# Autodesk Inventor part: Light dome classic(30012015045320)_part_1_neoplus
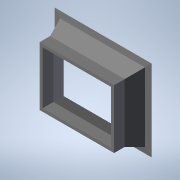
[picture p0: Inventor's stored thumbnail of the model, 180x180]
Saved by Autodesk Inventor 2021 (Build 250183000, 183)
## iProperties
Created: 2026-04
Part Number: Light dome classic(30012015045320)_part_1_neoplus
Material: Generic
Catalog Web Link: www.3dfindit.com
Description: Light dome classic_part_1_neoplus-
Vendor: KINGSPAN
Document SubType Name: Modeling
Designer: psAdmin
Manufacturer: KINGSPAN
Mass: 152663 g
Surface Area: 72270.1 cm^2
Volume: 152663 cm^3
Density: 1 g/cm^3
Appearance: PSOLRGB-255-255-255
Category: PARTsolutions
Company: KINGSPAN
Title: Light dome classic(30012015045320)_part_1_neoplus
Author: Cadenas PARTsolutions
PSOL_IDENT_0: {$CADENAS_DATA/23d-libs/kingspan_kla/light_dome_classic_neoplus/parts/part_1.prj},297 {VTYP=3D},{NB=
PSOL_IDENT_1: Light dome classic(30012015045320)_part_1_neoplus},{LINA=Light dome classic(30012015045320)_part_1_n
PSOL_IDENT_2: eoplus},{NN=Light dome classic_part_1_neoplus},{DATE=20.03.2025 09:30:52},{GEOMDATE=03.07.2024 07:48
PSOL_IDENT_3: :00},{VERSION=},{LINEID=10},{WBVAR=LODLEVEL,L,W,DP,OP,BA,INS,RT},{WBNUMERIC=W,RT}  {NB=Light dome cl
PSOL_IDENT_4: assic(30012015045320)_part_1_neoplus},{LINA=Light dome classic(30012015045320)_part_1_neoplus},{KT=D
PSOL_IDENT_5: UMMY},{IDNR=},{PN=Light dome classic},{LODLEVEL=300},{L=120},{W=150},{DRIVE=1},{WX=120,150,180,240,2
PSOL_IDENT_6: 70,300},{DP=4},{OP=5},{BA=3},{INS=2},{INSX='2','without insulation'},{OPX='5','Pneumatic - NRWG F.6
PSOL_IDENT_7: LK'},{LX=1200},{XWX=1500},{HEI=1181.607},{BAX='1', 'PVC base 15 cm','2', 'PVC base 30 cm', '3', 'PVC
PSOL_IDENT_8: base 50 cm' , '4', 'Metal base single skin (steel), 30 cm', '5' , 'Metal base single skin (steel),
PSOL_IDENT_9: 40 cm', '6' , 'Metal base single skin (steel), 50 cm', '7' , 'Metal base double skin (aluminum), 30
PSOL_IDENT_10: cm', '8' , 'Metal base double skin (aluminum), 40 cm', '9' , 'Metal base double skin (aluminum), 50
PSOL_IDENT_11: cm', '10', 'Steel base 30 cm', '11' , 'Steel base 40 cm', '12', 'Steel base 50 cm', '13' , 'AK30 AL/
PSOL_IDENT_12: AL', '14' , 'AK40 AL/AL', '15' , 'AK50 AL/AL', '16' , 'AK50 ST-TG'},{RT=0}
NB: Light dome classic(30012015045320)_part_1_neoplus
NN: Light dome classic_part_1_neoplus
NBSYN: $PN.($LODLEVEL.$L.$W.$DP.$OP.$BA.$INS.$RT.)_part_1_neoplus
LINA: Light dome classic(30012015045320)_part_1_neoplus
CATALOG: Light + Air
PN: Light dome classic
LODLEVEL: 300
L: 120
W: 150
DP: NSHE
OP: Pneumatic - NRWG F.6 LK
BA: PVC base 50 cm
INS: without insulation
RT: 0
SUPPLIER: KINGSPAN
ARTICLENO: Light dome classic(30012015045320)_part_1_neoplus
BOMINFO: Light dome classic(30012015045320)_part_1_neoplus
CREATOR: CADENAS GmbH
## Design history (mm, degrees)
sketch "Sketch_1"
  geometry: L1 (-650.529, 500)-(-707.495, 500); L2 (-707.495, 500)-(-707.495, 300); L3 (-707.495, 300)-(-805.041, 12.062); L4 (-805.041, 12.062)-(-920.088, 1.996); L5 (-920.001, 0)-(-750, 0); L6 (-750, 0)-(-650.529, 293.622); L7 (-650.529, 293.622)-(-650.529, 500); A1 r 1 centre (-920.001, 1) between (-920.088, 1.996) and (-920.001, 0)
  constraints: 14 end point, 2 point on circle, 1 centre point
extrude "Extrusion1" join sketch "Sketch_1" stored distance "d0" = 2400; taper "d1" = 0 deg
sketch "Sketch_2"
  geometry: L1 (500.529, 500)-(500.529, 293.622); L2 (500.529, 293.622)-(600, 0); L3 (600, 0)-(770.001, 0); L4 (770.088, 1.996)-(655.041, 12.062); L5 (655.041, 12.062)-(557.495, 300); L6 (557.495, 300)-(557.495, 500); L7 (557.495, 500)-(500.529, 500); A1 r 1 centre (770.001, 1) between (770.001, 0) and (770.088, 1.996)
  constraints: 14 end point, 2 point on circle, 1 centre point
extrude "Extrusion2" join sketch "Sketch_2" stored distance "d2" = 3000; taper "d3" = 0 deg
sketch "Sketch_3"
  geometry: L1 (920.088, 1.996)-(805.041, 12.062); L2 (805.041, 12.062)-(707.495, 300); L3 (707.495, 300)-(707.495, 500); L4 (707.495, 500)-(650.529, 500); L5 (650.529, 500)-(650.529, 293.622); L6 (650.529, 293.622)-(750, 0); L7 (750, 0)-(920.001, 0); A1 r 1 centre (920.001, 1) between (920.001, 0) and (920.088, 1.996)
  constraints: 14 end point, 2 point on circle, 1 centre point
extrude "Extrusion3" join sketch "Sketch_3" stored distance "d4" = 2400; taper "d5" = 0 deg
sketch "Sketch_4"
  geometry: L1 (-500.529, 500)-(-557.495, 500); L2 (-557.495, 500)-(-557.495, 300); L3 (-557.495, 300)-(-655.041, 12.062); L4 (-655.041, 12.062)-(-770.088, 1.996); L5 (-770.001, 0)-(-600, 0); L6 (-600, 0)-(-500.529, 293.622); L7 (-500.529, 293.622)-(-500.529, 500); A1 r 1 centre (-770.001, 1) between (-770.088, 1.996) and (-770.001, 0)
  constraints: 14 end point, 2 point on circle, 1 centre point
extrude "Extrusion4" join sketch "Sketch_4" stored distance "d6" = 3000; taper "d7" = 0 deg
sketch "Sketch_5"
  geometry: L1 (-650, 600)-(-1500, 600); L2 (-1500, 600)-(-1500, -30); L3 (-1500, -30)-(-819.29, -30); L4 (-819.29, -30)-(-809.127, 0); L5 (-809.127, 0)-(-920.001, 0); L6 (-920.088, 1.996)-(-805.041, 12.062); L7 (-805.041, 12.062)-(-707.495, 300); L8 (-707.495, 300)-(-707.495, 500); L9 (-707.495, 500)-(-650, 500); L10 (-650, 500)-(-650, 600); A1 r 1 centre (-920.001, 1) between (-920.088, 1.996) and (-920.001, 0)
  constraints: 20 end point, 2 point on circle, 1 centre point
extrude "Extrusion5" cut sketch "Sketch_5" stored distance "d8" = 2400; taper "d9" = 0 deg
sketch "Sketch_6"
  geometry: L1 (1500, -30)-(1500, 600); L2 (1500, 600)-(650, 600); L3 (650, 600)-(650, 500); L4 (650, 500)-(707.495, 500); L5 (707.495, 500)-(707.495, 300); L6 (707.495, 300)-(805.041, 12.062); L7 (805.041, 12.062)-(920.088, 1.996); L8 (920.001, 0)-(809.127, 0); L9 (809.127, 0)-(819.29, -30); L10 (819.29, -30)-(1500, -30); A1 r 1 centre (920.001, 1) between (920.001, 0) and (920.088, 1.996)
  constraints: 20 end point, 2 point on circle, 1 centre point
extrude "Extrusion6" cut sketch "Sketch_6" stored distance "d10" = 2400; taper "d11" = 0 deg
sketch "Sketch_7"
  geometry: L1 (1200, 600)-(500, 600); L2 (500, 600)-(500, 500); L3 (500, 500)-(557.495, 500); L4 (557.495, 500)-(557.495, 300); L5 (557.495, 300)-(655.041, 12.062); L6 (655.041, 12.062)-(770.088, 1.996); L7 (770.001, 0)-(659.127, 0); L8 (659.127, 0)-(669.29, -30); L9 (669.29, -30)-(1200, -30); L10 (1200, -30)-(1200, 600); A1 r 1 centre (770.001, 1) between (770.001, 0) and (770.088, 1.996)
  constraints: 20 end point, 2 point on circle, 1 centre point
extrude "Extrusion7" cut sketch "Sketch_7" stored distance "d12" = 3000; taper "d13" = 0 deg
sketch "Sketch_9"
  geometry: L1 (-1200, 600)-(-1200, -30); L2 (-1200, -30)-(-669.29, -30); L3 (-669.29, -30)-(-659.127, 0); L4 (-659.127, 0)-(-770.001, 0); L5 (-770.088, 1.996)-(-655.041, 12.062); L6 (-655.041, 12.062)-(-557.495, 300); L7 (-557.495, 300)-(-557.495, 500); L8 (-557.495, 500)-(-500, 500); L9 (-500, 500)-(-500, 600); L10 (-500, 600)-(-1200, 600); A1 r 1 centre (-770.001, 1) between (-770.088, 1.996) and (-770.001, 0)
  constraints: 20 end point, 2 point on circle, 1 centre point
extrude "Extrusion8" cut sketch "Sketch_9" stored distance "d14" = 3000; taper "d15" = 0 deg
node "1_XY"
node "1_YZ"
node "1_ZX"
node "1_X"
node "1_Y"
node "1_Z"
node "1_Center"
node "IP_for_dummy_XY"
node "IP_for_dummy_YZ"
node "IP_for_dummy_ZX"
node "IP_for_dummy_X"
node "IP_for_dummy_Y"
node "IP_for_dummy_Z"
node "IP_for_dummy_Center"
node "IP_for_part_10_1_XY"
node "IP_for_part_10_1_YZ"
node "IP_for_part_10_1_ZX"
node "IP_for_part_10_1_X"
node "IP_for_part_10_1_Y"
node "IP_for_part_10_1_Z"
node "IP_for_part_10_1_Center"
node "IP_for_part_2_XY"
node "IP_for_part_2_YZ"
node "IP_for_part_2_ZX"
node "IP_for_part_2_X"
node "IP_for_part_2_Y"
node "IP_for_part_2_Z"
node "IP_for_part_2_Center"
node "light_dome_classic_XY"
node "light_dome_classic_YZ"
node "light_dome_classic_ZX"
node "light_dome_classic_X"
node "light_dome_classic_Y"
node "light_dome_classic_Z"
node "light_dome_classic_Center"
body "Solid1"
other parameters: "d16" = 0, "d17" = 0, "d18" = 0, "d19" = 0
